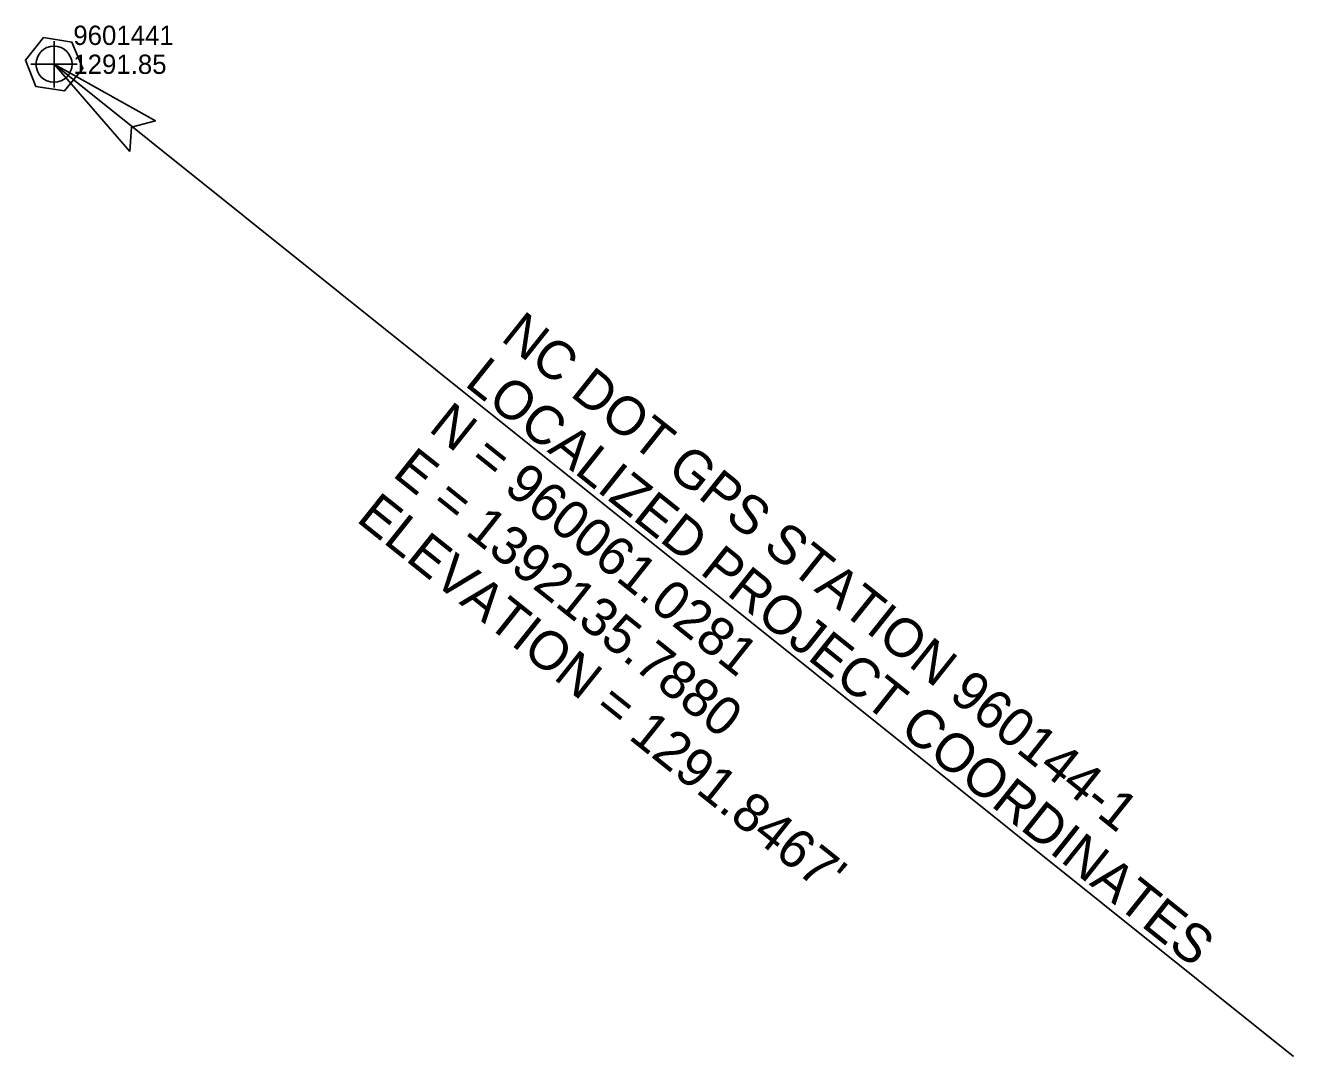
# Model space of a CAD drawing. Extents: x 1390773 to 1392296, y 959928 to 960736.
# Drawn here: x 1392132.1 to 1392296.5, y 959932.5 to 960066.1 of the extents above; entities that cross this region are included whole.
import ezdxf

# ---------------------------------------------------------------- set-up
doc = ezdxf.new("R2010")
doc.units = 0
for name, color, linetype in [('Cogo Default Point CELL', 7, 'Continuous'), ('COGO Default Point Elevation', 7, 'Continuous'), ('COGO Default Point Number', 7, 'Continuous'), ('CTL GPS Vertical CELL', 7, 'Continuous'), ('CTL GPS Vertical Text', 7, 'Continuous'), ('Default', 7, 'Continuous'), ('Old_Level_11', 7, 'Continuous')]:
    doc.layers.add(name, color=color, linetype=linetype)

msp = doc.modelspace()

# ---------------------------------------------------------------- linework, layer by layer
at = {"layer": 'Cogo Default Point CELL'}
for points in [[(1392135.79, 960064.03), (1392135.79, 960061.03)], [(1392132.79, 960061.03), (1392135.79, 960061.03)], [(1392135.79, 960061.03), (1392138.79, 960061.03)], [(1392135.79, 960061.03), (1392135.79, 960058.03)]]:
    msp.add_lwpolyline(points, dxfattribs=at)
msp.add_circle((1392135.79, 960061.03), 2.34, dxfattribs=at)
at = {"layer": 'CTL GPS Vertical CELL'}
msp.add_line((1392135.79, 960061.03), (1392135.79, 960061.03), dxfattribs=at)
msp.add_lwpolyline([(1392134.43, 960064.51), (1392138.1, 960063.9), (1392139.53, 960060.47), (1392137.16, 960057.59), (1392133.45, 960058.14), (1392132.08, 960061.56)], close=True, dxfattribs=at)
at = {"layer": 'Default'}
msp.add_line((1392135.79, 960061.03), (1392296.45, 959932.49), dxfattribs=at)
at = {"layer": 'Old_Level_11'}
msp.add_lwpolyline([(1392145.62, 960049.75), (1392135.79, 960061.03), (1392148.94, 960053.7), (1392145.83, 960052.86)], close=True, dxfattribs=at)

# ---------------------------------------------------------------- texts
at = {"layer": 'COGO Default Point Elevation'}
msp.add_text('1291.85', height=2.5, dxfattribs=at).set_placement((1392138.29, 960059.78))
at = {"layer": 'COGO Default Point Number'}
msp.add_text('9601441', height=2.5, dxfattribs=at).set_placement((1392138.29, 960063.53))
at = {"layer": 'CTL GPS Vertical Text'}
for s, p in [('NC DOT GPS STATION 960144-1', (1392193.54, 960025.36)), ('LOCALIZED PROJECT COORDINATES', (1392188.86, 960019.5)), ('N = 960061.0281', (1392184.18, 960013.64)), ('E = 1392135.7880', (1392179.5, 960007.78)), ("ELEVATION = 1291.8467'", (1392174.82, 960001.92))]:
    msp.add_text(s, height=5, rotation=321.3969, dxfattribs=at).set_placement(p)

doc.saveas('drawing.dxf')
